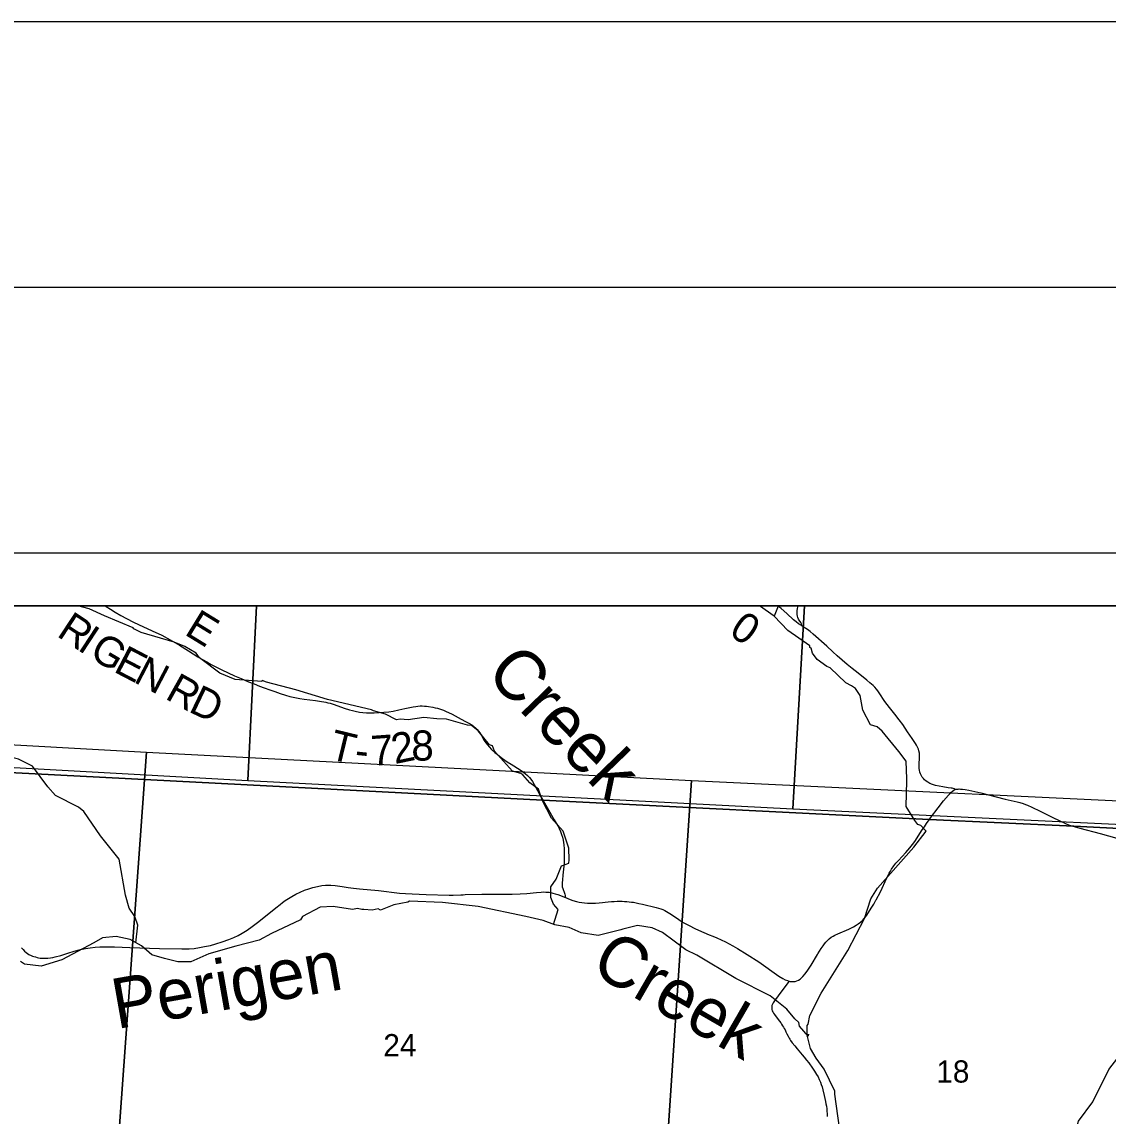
# Model space of a CAD drawing. Extents: x 0 to 34, y 0 to 22.
# Drawn here: x 25.071 to 27.118, y 19.939 to 22 of the extents above; entities that cross this region are included whole.
import ezdxf

# ---------------------------------------------------------------- set-up
doc = ezdxf.new("R2010")
doc.units = 0
for name, color, linetype in [('GM_X_County_Road', 7, 'Continuous'), ('GM_X_County_Road_Text', 7, 'Continuous'), ('GM_X_County_Text', 7, 'Continuous'), ('GM_X_Minor_River', 7, 'Continuous'), ('GM_X_Minor_River_Text', 7, 'Continuous'), ('GM_X_Section', 7, 'Continuous'), ('GM_X_Section_Text', 7, 'Continuous'), ('GM_X_State_Route', 7, 'Continuous'), ('GM_X_State_Shield', 7, 'Continuous'), ('GM_X_Township_Road', 7, 'Continuous'), ('GM_X_Township_Road_Text', 7, 'Continuous'), ('SH_Border', 7, 'Continuous'), ('SH_Cut_Line', 7, 'Continuous'), ('SH_Data', 7, 'Continuous')]:
    doc.layers.add(name, color=color, linetype=linetype)

msp = doc.modelspace()

# ---------------------------------------------------------------- linework, layer by layer
at = {"layer": 'GM_X_County_Road'}
for points in [[(26.8301, 20.5536), (26.828, 20.5549), (26.8262, 20.5557), (26.8245, 20.5562), (26.8227, 20.5565), (26.8169, 20.5573), (26.8072, 20.5586), (26.8, 20.5599), (26.7933, 20.5615), (26.7873, 20.5634), (26.7826, 20.5653), (26.7787, 20.5674), (26.7755, 20.5696), (26.7726, 20.572), (26.7704, 20.5743), (26.7681, 20.5774), (26.7661, 20.5807), (26.7648, 20.5836), (26.7637, 20.5867), (26.763, 20.59), (26.7626, 20.5932), (26.7624, 20.5974), (26.7625, 20.6023), (26.763, 20.6126), (26.763, 20.6178), (26.7627, 20.6225), (26.762, 20.6264), (26.7608, 20.6301), (26.7594, 20.6335), (26.7574, 20.6371), (26.7552, 20.6407), (26.7492, 20.6499), (26.7405, 20.6626), (26.7314, 20.6762), (26.7246, 20.6852), (26.7162, 20.6959), (26.7065, 20.7082), (26.6976, 20.7199), (26.6871, 20.7357), (26.6846, 20.7395), (26.6821, 20.7428), (26.6789, 20.7464), (26.6755, 20.7497), (26.6696, 20.7548), (26.6635, 20.7601), (26.6475, 20.7728), (26.6359, 20.7821), (26.6267, 20.7896), (26.6078, 20.8058), (26.5996, 20.8133), (26.5881, 20.8238), (26.5624, 20.8468), (26.5569, 20.8513), (26.5518, 20.8553), (26.5458, 20.8593), (26.5414, 20.8621), (26.5407, 20.8626), (26.5351, 20.8662), (26.5303, 20.8697), (26.5258, 20.8734), (26.5127, 20.8854), (26.5023, 20.8948), (26.4961, 20.9)], [(26.5414, 20.8621), (26.5411, 20.8637), (26.5407, 20.8657), (26.5401, 20.8672), (26.5393, 20.8686), (26.5365, 20.8728), (26.5352, 20.8749), (26.5339, 20.8779), (26.533, 20.8807), (26.5325, 20.8837), (26.5322, 20.8869), (26.5324, 20.8906), (26.5331, 20.8948), (26.5344, 20.9)], [(26.5173, 20.1927), (26.5, 20.1693), (26.4885, 20.1539), (26.4873, 20.152), (26.486, 20.1496), (26.485, 20.1471), (26.4845, 20.1446), (26.4844, 20.1419)], [(26.4844, 20.1419), (26.4847, 20.1394), (26.4853, 20.1371), (26.4864, 20.1348), (26.4877, 20.1326), (26.4898, 20.1297), (26.4968, 20.1205), (26.5015, 20.114), (26.5031, 20.1117), (26.505, 20.1089), (26.5066, 20.1063), (26.5082, 20.1035), (26.5096, 20.1009), (26.5113, 20.0976), (26.5131, 20.0938), (26.5153, 20.0893), (26.5172, 20.0855), (26.5185, 20.0832), (26.5201, 20.0808), (26.5233, 20.0763), (26.5278, 20.0707), (26.5323, 20.0652), (26.542, 20.054), (26.5458, 20.0494), (26.5501, 20.0442), (26.5543, 20.0389), (26.5616, 20.0289), (26.5652, 20.0235), (26.5691, 20.017), (26.5717, 20.0124), (26.574, 20.0077), (26.5762, 20.0027), (26.5779, 19.9981), (26.5793, 19.9938), (26.5809, 19.9883), (26.5833, 19.9776), (26.5856, 19.9663), (26.5866, 19.9615), (26.5874, 19.9571), (26.5881, 19.9524), (26.5886, 19.9476), (26.5889, 19.9426), (26.5891, 19.9381)]]:
    msp.add_lwpolyline(points, dxfattribs=at)
at = {"layer": 'GM_X_County_Text'}
msp.add_lwpolyline([(28.6466, 20.9), (23.8372, 20.9), (23.8372, 20.6485), (24.4417, 20.6174), (26.0533, 20.5337), (26.781, 20.4973), (27.0539, 20.4845), (27.8401, 20.4449), (28.6062, 20.4055)], close=True, dxfattribs=at)
msp.add_lwpolyline([(28.4159, 17.3358), (28.4427, 17.7695), (28.4677, 18.1732), (28.5249, 19.1245), (28.5443, 19.4375), (28.5808, 20.0106), (28.6062, 20.4055), (27.8401, 20.4449), (27.0539, 20.4845), (26.781, 20.4973), (26.0533, 20.5337), (24.4417, 20.6174), (23.8372, 20.6485), (23.8372, 14.4177)], dxfattribs=at)
at = {"layer": 'GM_X_Minor_River'}
msp.add_line((26.4897, 20.8811), (26.4971, 20.9), dxfattribs=at)
for points in [[(25.2864, 20.2653), (25.2899, 20.2985), (25.2843, 20.3146), (25.2738, 20.3301), (25.267, 20.3546), (25.2547, 20.4223), (25.2197, 20.4667), (25.1882, 20.5125), (25.1779, 20.5208), (25.1347, 20.5427), (25.1201, 20.5587), (25.0914, 20.5976), (25.0653, 20.6109), (25.0406, 20.617), (25.0244, 20.6327), (25.0194, 20.6416), (24.9986, 20.6647), (24.9808, 20.6786), (24.9092, 20.7101), (24.8788, 20.7304), (24.8447, 20.7904), (24.8211, 20.8215), (24.7261, 20.9)], [(26.0734, 20.2996), (26.082, 20.3275), (26.0733, 20.3378), (26.068, 20.3507), (26.0684, 20.3708), (26.0782, 20.3849), (26.0884, 20.41), (26.1024, 20.415), (26.1027, 20.4215), (26.1023, 20.4435), (26.0917, 20.4754), (26.0698, 20.5001), (26.0523, 20.5323), (26.0451, 20.5543), (26.0289, 20.5665), (26.0156, 20.5813), (26.0118, 20.5843), (25.996, 20.5884), (25.9623, 20.626), (25.9581, 20.6359), (25.9528, 20.6377), (25.9316, 20.6643), (25.9188, 20.6745), (25.9112, 20.6749), (25.8715, 20.6862), (25.8537, 20.6873), (25.8292, 20.6895), (25.7997, 20.6853), (25.7842, 20.6864), (25.7774, 20.6848), (25.7569, 20.6958), (25.7339, 20.7022), (25.7301, 20.7041), (25.6473, 20.7237), (25.5879, 20.7418), (25.5327, 20.7561), (25.5244, 20.7595), (25.5236, 20.7572), (25.4734, 20.7612), (25.4446, 20.7733), (25.4064, 20.8021), (25.3996, 20.8109), (25.3788, 20.8233), (25.3584, 20.8313), (25.296, 20.8497), (25.2824, 20.8566), (25.2809, 20.8585), (25.2272, 20.8811), (25.198, 20.8944), (25.1768, 20.9)], [(26.6151, 19.894), (26.6037, 19.9799), (26.6036, 19.9856), (26.5836, 20.027), (26.5681, 20.0475), (26.5575, 20.0657), (26.551, 20.0908), (26.5514, 20.109), (26.5532, 20.112), (26.5566, 20.1284), (26.5778, 20.1703), (26.628, 20.2506), (26.6593, 20.3111), (26.6713, 20.348), (26.6838, 20.3678), (26.7521, 20.4451), (26.7756, 20.4755), (26.7653, 20.4858), (26.7597, 20.4877), (26.7544, 20.4953), (26.7381, 20.5218), (26.7388, 20.5701), (26.7392, 20.5739), (26.738, 20.6074), (26.724, 20.6256), (26.6926, 20.6635), (26.6831, 20.6722), (26.6706, 20.676), (26.6562, 20.7033), (26.6509, 20.7311), (26.6422, 20.7443), (26.6347, 20.7489), (26.6241, 20.7549), (26.5949, 20.783), (26.5885, 20.7853), (26.5703, 20.7985), (26.5616, 20.8107), (26.559, 20.8202), (26.5563, 20.8213), (26.556, 20.8247), (26.5147, 20.8531), (26.489, 20.8804), (26.4615, 20.9)], [(25.802, 20.3432), (25.7985, 20.3416), (25.7724, 20.3363), (25.7475, 20.3267), (25.7426, 20.329), (25.7316, 20.3263), (25.7161, 20.3278), (25.7123, 20.3277), (25.704, 20.3296), (25.6942, 20.3277), (25.6583, 20.3333), (25.6333, 20.3321), (25.6001, 20.3145), (25.5967, 20.3085), (25.5419, 20.2825), (25.5185, 20.2702), (25.4746, 20.2584), (25.4236, 20.2445), (25.39, 20.2293), (25.3866, 20.2292), (25.3654, 20.2292), (25.3404, 20.2356), (25.3162, 20.2424), (25.297, 20.2594), (25.2754, 20.2712), (25.2493, 20.2772), (25.2236, 20.2745), (25.207, 20.2649), (25.1469, 20.2328), (25.1076, 20.2209), (25.0766, 20.2247), (25.069, 20.23)], [(26.5515, 20.0887), (26.5536, 20.093), (26.5533, 20.0889), (26.537, 20.1082), (26.5355, 20.115), (26.5279, 20.1215), (26.5132, 20.1401), (26.4818, 20.1651), (26.4171, 20.198), (26.3433, 20.2419), (26.3225, 20.2521), (26.2786, 20.2847), (26.2594, 20.293), (26.2314, 20.2975), (26.2038, 20.291), (26.2, 20.2894), (26.1577, 20.2787), (26.1255, 20.2839), (26.1025, 20.2941), (26.076, 20.2986), (26.0537, 20.3073), (26.0212, 20.3145), (25.9316, 20.3336), (25.8639, 20.3407), (25.802, 20.3432)], [(26.9263, 19.6632), (26.9309, 19.6802), (26.9584, 19.7286), (26.9754, 19.752), (27.0152, 19.8051), (27.0402, 19.8574), (27.051, 19.8905), (27.0628, 19.9288), (27.0896, 19.9656), (27.1198, 20.0265), (27.1878, 20.1143), (27.2041, 20.1286)]]:
    msp.add_lwpolyline(points, dxfattribs=at)
at = {"layer": 'GM_X_Section'}
for points in [[(24.2561, 20.6827), (25.3065, 20.6239), (25.2325, 19.5985), (24.2052, 19.6482)], [(25.3065, 20.6239), (26.3334, 20.5711), (26.2655, 19.5533), (25.2325, 19.5985)], [(26.3334, 20.5711), (27.3906, 20.5203), (27.3196, 19.501), (26.2655, 19.5533)]]:
    msp.add_lwpolyline(points, close=True, dxfattribs=at)
at = {"layer": 'GM_X_State_Route'}
for points in [[(26.7812, 20.4968), (26.7839, 20.5006), (26.7984, 20.5196), (26.8084, 20.5325), (26.8173, 20.5432), (26.8199, 20.5459), (26.8222, 20.5483), (26.825, 20.5506), (26.8276, 20.5523), (26.8301, 20.5536)], [(26.8301, 20.5536), (26.8319, 20.5543), (26.834, 20.5546), (26.836, 20.5548), (26.838, 20.5549), (26.84, 20.5548), (26.8439, 20.5544), (26.8488, 20.5537), (26.8562, 20.5524), (26.8786, 20.5476), (26.9243, 20.5359), (26.9414, 20.532), (26.9467, 20.5307), (26.9521, 20.5292), (26.9582, 20.5273), (26.9627, 20.5258), (26.9665, 20.5243), (26.9746, 20.5208), (26.9774, 20.5194), (26.988, 20.5142), (27.014, 20.501), (27.0378, 20.4897), (27.0437, 20.4873), (27.0477, 20.4858), (27.0541, 20.484)], [(26.6806, 20.3451), (26.6811, 20.346), (26.6892, 20.3613), (26.7015, 20.3876), (26.7038, 20.3921), (26.706, 20.3964), (26.708, 20.3999), (26.7105, 20.4038), (26.7147, 20.4099), (26.7185, 20.4148), (26.7234, 20.4204), (26.7369, 20.4349), (26.7448, 20.4437), (26.7499, 20.4501), (26.7542, 20.4562), (26.768, 20.4777), (26.7722, 20.4838), (26.7764, 20.4899), (26.7812, 20.4968)], [(27.0541, 20.484), (27.065, 20.4808), (27.1033, 20.4709), (27.1506, 20.4579)], [(25.0709, 20.2557), (25.0739, 20.2523), (25.0766, 20.2495), (25.0795, 20.2468), (25.0821, 20.2449), (25.0848, 20.2433), (25.0891, 20.2411), (25.0917, 20.24), (25.0942, 20.2392), (25.0971, 20.2383), (25.1001, 20.2375), (25.1029, 20.2369), (25.1058, 20.2364), (25.1084, 20.2361), (25.111, 20.2359), (25.1135, 20.2358), (25.116, 20.2358), (25.1205, 20.236), (25.1252, 20.2365), (25.1295, 20.2373), (25.1341, 20.2383), (25.1447, 20.2413), (25.1582, 20.2456), (25.17, 20.2492), (25.1822, 20.2522), (25.1912, 20.2541), (25.2003, 20.2556), (25.2096, 20.2568), (25.2184, 20.2573), (25.2267, 20.2576), (25.2358, 20.2577), (25.2457, 20.2574), (25.2749, 20.2565), (25.331, 20.2545), (25.3728, 20.2535), (25.3799, 20.2536), (25.3867, 20.2539), (25.3959, 20.2546), (25.4064, 20.2561), (25.4156, 20.2578), (25.4266, 20.2602), (25.4368, 20.263), (25.4487, 20.2666), (25.4617, 20.271), (25.4709, 20.2749), (25.4788, 20.2788), (25.4864, 20.2831), (25.4958, 20.2891), (25.5055, 20.2959), (25.518, 20.3052), (25.5503, 20.3309), (25.5579, 20.337), (25.5629, 20.341), (25.5679, 20.3447), (25.5738, 20.3486), (25.5802, 20.3524), (25.5878, 20.3566), (25.5961, 20.3606), (25.6041, 20.364), (25.6122, 20.367), (25.6199, 20.3693), (25.6283, 20.3714), (25.6368, 20.3729), (25.6435, 20.3736), (25.6478, 20.3738), (25.6539, 20.3736), (25.6619, 20.3729), (25.6748, 20.3711), (25.6865, 20.3695), (25.6966, 20.3682), (25.7078, 20.367), (25.7435, 20.3638), (25.7828, 20.3587), (25.7945, 20.3577), (25.8067, 20.357), (25.8331, 20.356), (25.8768, 20.3548), (25.884, 20.3547), (25.8984, 20.3554), (25.9029, 20.3557), (25.9069, 20.3559), (25.9383, 20.3565), (25.9742, 20.3566), (25.9954, 20.3568), (26.0105, 20.3574), (26.023, 20.358), (26.0412, 20.3595), (26.0502, 20.3605), (26.0551, 20.3608), (26.0588, 20.3607), (26.0621, 20.3606), (26.0654, 20.3603), (26.0683, 20.3599), (26.0723, 20.3588), (26.0766, 20.3574), (26.0816, 20.3558), (26.0956, 20.3501), (26.1044, 20.3466), (26.11, 20.3447), (26.1166, 20.3428), (26.1219, 20.3415), (26.1266, 20.3407), (26.1318, 20.3402), (26.1374, 20.3399), (26.1522, 20.3399), (26.1596, 20.3402), (26.1656, 20.3407), (26.1709, 20.3414), (26.1765, 20.3421), (26.1824, 20.3428), (26.1877, 20.3431), (26.1935, 20.3434), (26.198, 20.3434), (26.2027, 20.3433), (26.2069, 20.3431), (26.2114, 20.3429), (26.216, 20.3424), (26.22, 20.3419), (26.224, 20.3414), (26.2289, 20.3404), (26.234, 20.3393), (26.2407, 20.3376), (26.2665, 20.3315), (26.2709, 20.3304), (26.2755, 20.3289), (26.2793, 20.3275), (26.2829, 20.3257), (26.2892, 20.3223), (26.2955, 20.3183), (26.3092, 20.3088), (26.3166, 20.3041), (26.3214, 20.3012), (26.3286, 20.2974), (26.3393, 20.2923), (26.3467, 20.289), (26.3666, 20.2803), (26.3734, 20.2773), (26.3809, 20.2743), (26.3972, 20.2668), (26.4044, 20.2632), (26.4115, 20.2594), (26.42, 20.2543), (26.4379, 20.2432), (26.4599, 20.2291), (26.4981, 20.2025), (26.5055, 20.1978), (26.5099, 20.1954), (26.514, 20.1938), (26.5173, 20.1927), (26.5195, 20.1922), (26.522, 20.1919), (26.5253, 20.1919), (26.5285, 20.1923), (26.5316, 20.1932), (26.5352, 20.1947), (26.5378, 20.1965), (26.5408, 20.199), (26.5434, 20.2017), (26.5474, 20.2066), (26.5525, 20.2137), (26.5588, 20.223), (26.5706, 20.2429), (26.5716, 20.2445)], [(26.5716, 20.2445), (26.5776, 20.2541), (26.5812, 20.2595), (26.584, 20.2633), (26.5864, 20.2663), (26.5893, 20.2695), (26.593, 20.2727), (26.5967, 20.2755), (26.6001, 20.2775), (26.6037, 20.2795), (26.609, 20.2819), (26.6295, 20.291), (26.6385, 20.2952), (26.6434, 20.298), (26.6476, 20.3008), (26.6516, 20.3038), (26.6553, 20.307), (26.6595, 20.3115), (26.6638, 20.3173), (26.672, 20.3302), (26.6766, 20.3381), (26.6806, 20.3451)]]:
    msp.add_lwpolyline(points, dxfattribs=at)
at = {"layer": 'GM_X_State_Shield'}
for points in [[(25.5135, 20.9), (24.4676, 20.9), (24.4469, 20.6293), (25.4973, 20.5705)], [(26.5463, 20.9), (25.5135, 20.9), (25.4973, 20.5705), (26.5242, 20.5177)], [(27.6063, 20.9), (26.5463, 20.9), (26.5242, 20.5177), (27.5814, 20.4669)]]:
    msp.add_lwpolyline(points, close=True, dxfattribs=at)
at = {"layer": 'GM_X_Township_Road'}
for points in [[(25.2286, 20.9), (25.2301, 20.8989), (25.2383, 20.8936), (25.2471, 20.8882), (25.258, 20.8818), (25.2689, 20.8757), (25.2816, 20.8693), (25.2911, 20.8647), (25.3169, 20.8529), (25.3349, 20.8444), (25.3508, 20.8358), (25.3682, 20.8256), (25.3855, 20.8152), (25.4029, 20.8041), (25.4121, 20.7987), (25.42, 20.7941), (25.4282, 20.7895), (25.4384, 20.7843), (25.4485, 20.7792), (25.4601, 20.7736), (25.4723, 20.7681), (25.485, 20.7627), (25.4986, 20.757), (25.5089, 20.7527), (25.5193, 20.7486), (25.528, 20.7454), (25.5386, 20.7417), (25.5481, 20.7384), (25.5579, 20.735), (25.5685, 20.7315), (25.5763, 20.7293), (25.586, 20.7271), (25.5951, 20.7254), (25.6037, 20.7242), (25.6141, 20.7228), (25.6245, 20.7215), (25.636, 20.7199), (25.6402, 20.7192), (25.6444, 20.7183), (25.6483, 20.7173), (25.6522, 20.7162), (25.658, 20.7145), (25.6668, 20.7114), (25.6785, 20.7073), (25.6886, 20.7042), (25.6942, 20.7027), (25.6994, 20.7014), (25.7079, 20.6997), (25.7141, 20.6988), (25.721, 20.6983), (25.7276, 20.6981), (25.7355, 20.6983), (25.745, 20.6988), (25.7535, 20.6994), (25.7628, 20.7003), (25.7714, 20.7017), (25.7818, 20.7039), (25.7929, 20.7064), (25.8088, 20.7097), (25.8137, 20.7105), (25.8176, 20.711), (25.8221, 20.7113), (25.8259, 20.7113), (25.83, 20.7111), (25.834, 20.7107), (25.8379, 20.7102), (25.846, 20.7088), (25.8503, 20.7079), (25.8546, 20.7068), (25.8583, 20.7058), (25.8623, 20.7045), (25.8661, 20.7031), (25.8698, 20.7016), (25.882, 20.6955), (25.8935, 20.6894), (25.9062, 20.6829), (25.9138, 20.6787), (25.9192, 20.6754), (25.9233, 20.6725), (25.9262, 20.67), (25.9292, 20.6672), (25.9319, 20.6639), (25.9348, 20.6599), (25.9373, 20.6556), (25.9394, 20.6518), (25.9426, 20.6464), (25.9457, 20.6418), (25.9486, 20.6378), (25.9518, 20.6341), (25.9567, 20.6292), (25.9627, 20.6238), (25.967, 20.6202), (25.9713, 20.6167), (25.9773, 20.6122), (25.9815, 20.6092), (25.986, 20.6062), (25.9933, 20.6016), (26.0102, 20.5911), (26.0148, 20.588), (26.0197, 20.5842), (26.0244, 20.5801), (26.0278, 20.5765), (26.0306, 20.5732), (26.0334, 20.5691), (26.0369, 20.5632), (26.0432, 20.5518), (26.0465, 20.5458), (26.0497, 20.5399), (26.0535, 20.5332)], [(26.0535, 20.5332), (26.0611, 20.5199), (26.0744, 20.4968), (26.0812, 20.4854), (26.084, 20.4801), (26.0864, 20.4745), (26.0884, 20.4692), (26.0901, 20.4638), (26.0915, 20.4585), (26.0924, 20.4541), (26.0929, 20.4493), (26.0933, 20.4422), (26.0935, 20.4346), (26.0936, 20.4307), (26.0936, 20.4263), (26.0934, 20.421), (26.0932, 20.4155), (26.0928, 20.4097), (26.0922, 20.4038), (26.0916, 20.3983), (26.091, 20.3927), (26.09, 20.3836), (26.0895, 20.3779), (26.0894, 20.3754), (26.0896, 20.373), (26.0899, 20.3705), (26.0906, 20.3675), (26.0914, 20.3652), (26.0931, 20.3606), (26.0944, 20.3565), (26.095, 20.3542), (26.0952, 20.3528), (26.0956, 20.3501)]]:
    msp.add_lwpolyline(points, dxfattribs=at)
at = {"layer": 'SH_Border'}
msp.add_lwpolyline([(1.5, 21.5), (33.5, 21.5), (33.5, 0.5), (1.5, 0.5)], close=True, dxfattribs=at)
at = {"layer": 'SH_Cut_Line'}
msp.add_lwpolyline([(0, 0), (34, 0), (34, 22), (0, 22)], close=True, dxfattribs=at)
msp.add_lwpolyline([(30.6372, 20.9), (23.8372, 20.9), (23.8372, 14.4177)], dxfattribs=at)
at = {"layer": 'SH_Data'}
for points in [[(23.7372, 21), (30.7372, 21), (30.7372, 14), (23.7372, 14)], [(23.8372, 20.9), (30.6372, 20.9), (30.6372, 14.1), (23.8372, 14.1)]]:
    msp.add_lwpolyline(points, close=True, dxfattribs=at)

# ---------------------------------------------------------------- texts
at = {"layer": 'GM_X_County_Road_Text'}
msp.add_text('0', height=0.0568, rotation=325.0216, dxfattribs=at).set_placement((26.4015, 20.8469))
at = {"layer": 'GM_X_Minor_River_Text'}
for s, height, rotation, p in [('Creek', 0.0947, 314.0019, (25.943, 20.7704)), ('Creek', 0.09469, 330.0049, (26.1398, 20.2112)), ('Perigen', 0.0947, 10.0083, (25.2501, 20.1023))]:
    msp.add_text(s, height=height, rotation=rotation, dxfattribs=at).set_placement(p)
at = {"layer": 'GM_X_Section_Text'}
for s, p in [('24', (25.7526, 20.0512)), ('18', (26.7947, 20.0017))]:
    msp.add_text(s, height=0.04186, rotation=0, dxfattribs=at).set_placement(p)
at = {"layer": 'GM_X_Township_Road_Text'}
for s, rotation, p in [('R', 326.635, (25.1352, 20.8439)), ('E', 328.4839, (25.3758, 20.847)), ('I', 326.7269, (25.1743, 20.8182)), ('G', 329.3578, (25.1962, 20.8039)), ('E', 332.4783, (25.2422, 20.7768)), ('N', 332.4428, (25.2799, 20.7572)), ('R', 330.8612, (25.3393, 20.726)), ('D', 334.4086, (25.3835, 20.7015)), ('T', 346.3411, (25.6477, 20.6121)), ('7', 3.9594, (25.7311, 20.5981)), ('2', 11.512, (25.7741, 20.6016)), ('8', 359.9349, (25.8054, 20.6083)), ('-', 354.1829, (25.6973, 20.6006))]:
    msp.add_text(s, height=0.0568, rotation=rotation, dxfattribs=at).set_placement(p)

doc.saveas('drawing.dxf')
